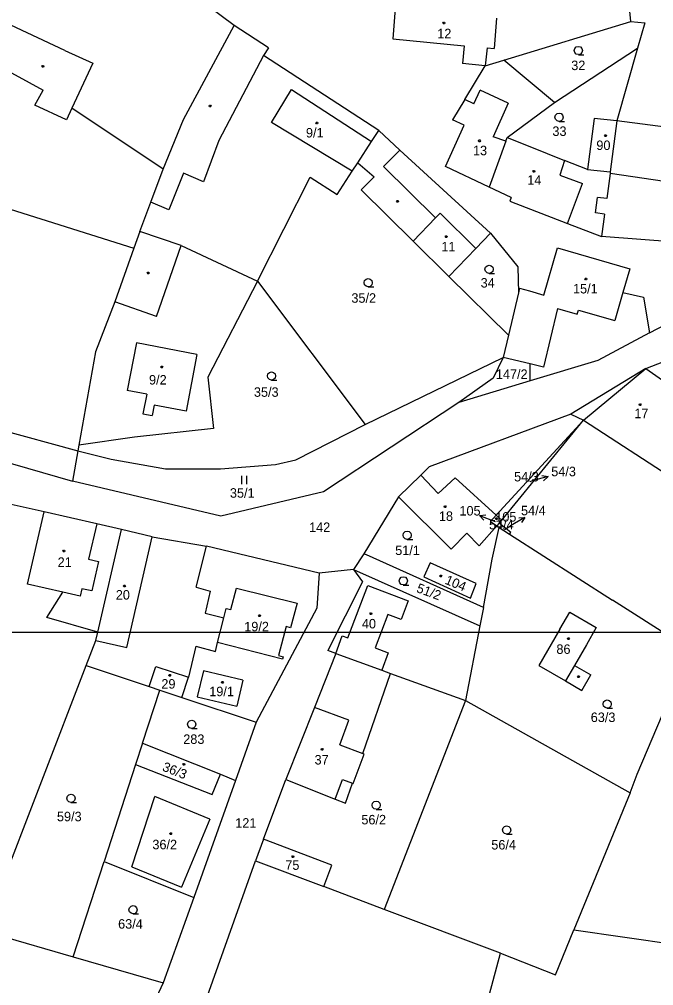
# Model space of a CAD drawing. Extents: x -752500 to -750336, y -1035826 to -1033500.
# Drawn here: x -751497.1 to -751383.4, y -1034563.3 to -1034390.2 of the extents above; entities that cross this region are included whole.
import ezdxf

# ---------------------------------------------------------------- set-up
doc = ezdxf.new("R2010")
doc.units = 0
for name, color, linetype in [('Default', 7, 'Continuous'), ('Hranice parcel', 7, 'Continuous'), ('ML1000', 7, 'Continuous'), ('Parcelní čísla', 7, 'Continuous'), ('Pop  PČ popisy', 7, 'Continuous'), ('Vnitřní kresba', 7, 'Continuous'), ('Značky budov', 7, 'Continuous'), ('Značky kultur', 7, 'Continuous')]:
    doc.layers.add(name, color=color, linetype=linetype)

# ---------------------------------------------------------------- blocks, each defined once
blk = doc.blocks.new('304')
at = {"layer": 'Default'}
blk.add_lwpolyline([(0, 0), (-0.38, 0.1), (-0.65, 0.37), (-0.75, 0.74), (-0.65, 1.11), (-0.38, 1.38), (-0.01, 1.48), (0.36, 1.38), (0.63, 1.11), (0.73, 0.73), (0.63, 0.35), (0.36, 0.08), (-0.02, -0.02), (0.98, -0.02)], dxfattribs=at)
blk = doc.blocks.new('306')
at = {"layer": 'Default'}
for p, q in [((-0.5, 1.5), (-0.5, 0)), ((0.5, 0), (0.5, 1.5))]:
    blk.add_line(p, q, dxfattribs=at)
blk = doc.blocks.new('10292')
at = {"layer": 'Default'}
blk.add_line((0, 3), (0, 0), dxfattribs=at)
blk.add_lwpolyline([(-0.5, 2), (0, 3), (0.5, 2)], dxfattribs=at)
blk = doc.blocks.new('402')
at = {"layer": 'Default'}
blk.add_lwpolyline([(0.09, 0.15), (0.18, 0), (0.09, -0.15), (-0.09, -0.15), (-0.18, 0), (-0.09, 0.15), (0.09, 0.15)], dxfattribs=at)

msp = doc.modelspace()

# ---------------------------------------------------------------- linework, layer by layer
at = {"layer": 'Hranice parcel'}
for p, q in [((-751387.54, -1034390.53), (-751392.08, -1034345.98)), ((-751458.62, -1034391.29), (-751473.53, -1034380.16)), ((-751429.76, -1034388.21), (-751430.17, -1034393.66)), ((-751411.64, -1034389.95), (-751412.05, -1034395.4)), ((-751467.72, -1034408.09), (-751458.62, -1034391.29)), ((-751452.45, -1034395.3), (-751458.62, -1034391.29)), ((-751410.32, -1034397.48), (-751387.54, -1034390.53)), ((-751387.54, -1034390.53), (-751385.01, -1034390.77)), ((-751385.01, -1034390.77), (-751386.32, -1034395.35)), ((-751430.17, -1034393.66), (-751417.38, -1034394.89)), ((-751452.45, -1034395.3), (-751453.35, -1034396.68)), ((-751417.38, -1034394.89), (-751417.69, -1034398.1)), ((-751413.31, -1034395.28), (-751413.62, -1034398.49)), ((-751413.31, -1034395.28), (-751412.05, -1034395.4)), ((-751401.21, -1034405.06), (-751386.32, -1034395.35)), ((-751386.32, -1034395.35), (-751390.04, -1034408.37)), ((-751503.65, -1034396.98), (-751492.88, -1034402.89)), ((-751432.72, -1034410.1), (-751453.35, -1034396.68)), ((-751413.62, -1034398.49), (-751417.69, -1034398.1)), ((-751417.32, -1034404.55), (-751413.62, -1034398.49)), ((-751413.62, -1034398.49), (-751410.32, -1034397.48)), ((-751401.21, -1034405.06), (-751410.32, -1034397.48)), ((-751494.34, -1034405.55), (-751492.88, -1034402.89)), ((-751488.67, -1034408.15), (-751494.34, -1034405.55)), ((-751417.32, -1034404.55), (-751419.52, -1034408.16)), ((-751409.71, -1034411.34), (-751401.21, -1034405.06)), ((-751487.71, -1034406.09), (-751488.67, -1034408.15)), ((-751471.36, -1034416.99), (-751487.71, -1034406.09)), ((-751545.55, -1034409.5), (-751476.6, -1034431.17)), ((-751471.36, -1034416.99), (-751467.72, -1034408.09)), ((-751420.76, -1034416.53), (-751417.41, -1034409.16)), ((-751417.41, -1034409.16), (-751419.52, -1034408.16)), ((-751394.13, -1034407.93), (-751395.28, -1034417.1)), ((-751390.04, -1034408.37), (-751394.13, -1034407.93)), ((-751390.04, -1034408.37), (-751391.23, -1034417.5)), ((-751375.36, -1034410.28), (-751390.04, -1034408.37)), ((-751434, -1034412.07), (-751432.72, -1034410.1)), ((-751428.93, -1034413.59), (-751432.72, -1034410.1)), ((-751436.49, -1034415.89), (-751434, -1034412.07)), ((-751409.94, -1034411.98), (-751412.91, -1034420.24)), ((-751409.94, -1034411.98), (-751409.71, -1034411.34)), ((-751409.71, -1034411.34), (-751405.63, -1034412.97)), ((-751405.63, -1034412.97), (-751399.43, -1034415.45)), ((-751412.7, -1034428.51), (-751428.93, -1034413.59)), ((-751437.46, -1034417.39), (-751436.49, -1034415.89)), ((-751436.49, -1034415.89), (-751433.53, -1034418.37)), ((-751395.28, -1034417.1), (-751399.43, -1034415.45)), ((-751473.58, -1034422.94), (-751471.36, -1034416.99)), ((-751440.17, -1034421.57), (-751437.46, -1034417.39)), ((-751412.91, -1034420.24), (-751420.76, -1034416.53)), ((-751395.28, -1034417.1), (-751391.23, -1034417.5)), ((-751391.27, -1034417.77), (-751391.87, -1034422.29)), ((-751391.23, -1034417.5), (-751391.27, -1034417.77)), ((-751454.46, -1034437.09), (-751444.98, -1034418.44)), ((-751444.98, -1034418.44), (-751440.17, -1034421.57)), ((-751433.53, -1034418.37), (-751435.87, -1034420.74)), ((-751426.54, -1034429.94), (-751435.87, -1034420.74)), ((-751408.96, -1034422.1), (-751412.91, -1034420.24)), ((-751475.53, -1034428.16), (-751473.58, -1034422.94)), ((-751408.96, -1034422.1), (-751409.23, -1034422.75)), ((-751409.23, -1034422.75), (-751398.89, -1034426.73)), ((-751393.88, -1034424.85), (-751393.51, -1034422.07)), ((-751391.87, -1034422.29), (-751393.51, -1034422.07)), ((-751392.24, -1034425.07), (-751393.88, -1034424.85)), ((-751392.24, -1034425.07), (-751392.78, -1034429.08)), ((-751398.89, -1034426.73), (-751392.78, -1034429.08)), ((-751475.53, -1034428.16), (-751476.6, -1034431.17)), ((-751468.14, -1034430.72), (-751475.53, -1034428.16)), ((-751415.29, -1034431.21), (-751412.7, -1034428.51)), ((-751412.7, -1034428.51), (-751407.8, -1034434.51)), ((-751420.13, -1034436.26), (-751426.54, -1034429.94)), ((-751370.18, -1034430.8), (-751392.78, -1034429.08)), ((-751476.6, -1034431.17), (-751480.01, -1034440.76)), ((-751468.14, -1034430.72), (-751454.46, -1034437.09)), ((-751420.13, -1034436.26), (-751415.29, -1034431.21)), ((-751403.15, -1034439.58), (-751400.71, -1034431.13)), ((-751400.71, -1034431.13), (-751387.74, -1034434.86)), ((-751407.8, -1034434.51), (-751407.68, -1034439.17)), ((-751387.74, -1034434.86), (-751388.96, -1034439.1)), ((-751454.46, -1034437.09), (-751463.33, -1034454.26)), ((-751454.46, -1034437.09), (-751435.16, -1034462.74)), ((-751420.13, -1034436.26), (-751409.47, -1034446.77)), ((-751407.48, -1034438.34), (-751407.68, -1034439.17)), ((-751407.48, -1034438.34), (-751405.73, -1034438.84)), ((-751405.73, -1034438.84), (-751403.15, -1034439.58)), ((-751407.68, -1034439.17), (-751409.47, -1034446.77)), ((-751388.96, -1034439.1), (-751385.3, -1034439.93)), ((-751385.3, -1034439.93), (-751384.22, -1034446.36)), ((-751384.22, -1034446.36), (-751372.58, -1034440.28)), ((-751480.01, -1034440.76), (-751483.5, -1034449.77)), ((-751409.47, -1034446.77), (-751410.41, -1034450.78)), ((-751384.22, -1034446.36), (-751393.43, -1034451.28)), ((-751384.87, -1034452.74), (-751371.68, -1034447.63)), ((-751483.5, -1034449.77), (-751486.47, -1034466.47)), ((-751435.16, -1034462.74), (-751410.41, -1034450.78)), ((-751410.41, -1034450.78), (-751412.2, -1034454.45)), ((-751405.6, -1034451.91), (-751410.41, -1034450.78)), ((-751405.57, -1034454.96), (-751405.6, -1034451.91)), ((-751393.43, -1034451.28), (-751405.57, -1034454.96)), ((-751384.87, -1034452.74), (-751398.3, -1034460.92)), ((-751552.12, -1034454.31), (-751487.6, -1034472.9)), ((-751463.33, -1034454.26), (-751462.3, -1034463.47)), ((-751412.2, -1034454.45), (-751418.39, -1034458.85)), ((-751529.41, -1034455.82), (-751486.65, -1034467.5)), ((-751405.57, -1034454.96), (-751418.39, -1034458.85)), ((-751418.39, -1034458.85), (-751442.6, -1034474.85)), ((-751398.3, -1034460.92), (-751423.67, -1034470.33)), ((-751398.3, -1034460.92), (-751396.05, -1034461.98)), ((-751447.56, -1034469.09), (-751435.16, -1034462.74)), ((-751396.05, -1034461.98), (-751411.67, -1034479.01)), ((-751410.68, -1034479.91), (-751396.05, -1034461.98)), ((-751396.05, -1034461.98), (-751362.12, -1034484.02)), ((-751462.3, -1034463.47), (-751476.48, -1034465.03)), ((-751486.47, -1034466.47), (-751486.65, -1034467.5)), ((-751476.48, -1034465.03), (-751486.47, -1034466.47)), ((-751486.65, -1034467.5), (-751487.6, -1034472.9)), ((-751486.65, -1034467.5), (-751480.67, -1034468.96)), ((-751480.67, -1034468.96), (-751470.96, -1034470.7)), ((-751461.06, -1034470.72), (-751451.22, -1034469.91)), ((-751451.22, -1034469.91), (-751447.56, -1034469.09)), ((-751470.96, -1034470.7), (-751461.06, -1034470.72)), ((-751425.2, -1034471.84), (-751429.16, -1034475.74)), ((-751423.67, -1034470.33), (-751425.2, -1034471.84)), ((-751461, -1034479.17), (-751487.6, -1034472.9)), ((-751442.6, -1034474.85), (-751461, -1034479.17)), ((-751492.7, -1034478.41), (-751498.58, -1034477.07)), ((-751429.16, -1034475.74), (-751435.4, -1034485.96)), ((-751429.16, -1034475.74), (-751419.74, -1034485.07)), ((-751495.67, -1034491.37), (-751492.7, -1034478.41)), ((-751483.25, -1034480.58), (-751492.7, -1034478.41)), ((-751412.72, -1034480.15), (-751411.67, -1034479.01)), ((-751412.72, -1034480.15), (-751411.57, -1034480.92)), ((-751410.68, -1034479.91), (-751411.67, -1034479.01)), ((-751411.13, -1034480.44), (-751411.57, -1034480.92)), ((-751411.13, -1034480.44), (-751410.68, -1034479.91)), ((-751409.07, -1034482.13), (-751411.13, -1034480.44)), ((-751478.83, -1034481.59), (-751483.25, -1034480.58)), ((-751483.06, -1034499.96), (-751478.83, -1034481.59)), ((-751473.31, -1034482.86), (-751478.83, -1034481.59)), ((-751419.74, -1034485.07), (-751416.92, -1034482.23)), ((-751416.92, -1034482.23), (-751414.72, -1034484.5)), ((-751414.72, -1034484.5), (-751411.57, -1034480.92)), ((-751412.37, -1034486.89), (-751411.13, -1034481.21)), ((-751411.57, -1034480.92), (-751411.13, -1034481.21)), ((-751411.13, -1034481.21), (-751409.3, -1034482.43)), ((-751409.3, -1034482.43), (-751409.07, -1034482.13)), ((-751473.31, -1034482.86), (-751463.61, -1034484.58)), ((-751409.3, -1034482.43), (-751390.83, -1034494.22)), ((-751465.41, -1034491.93), (-751463.61, -1034484.58)), ((-751443.41, -1034489.38), (-751463.61, -1034484.58)), ((-751435.4, -1034485.96), (-751437.22, -1034488.72)), ((-751434.91, -1034486.13), (-751435.4, -1034485.96)), ((-751413.93, -1034495.54), (-751434.91, -1034486.13)), ((-751413.93, -1034495.54), (-751412.37, -1034486.89)), ((-751437.22, -1034488.72), (-751443.41, -1034489.38)), ((-751437.22, -1034488.72), (-751414.59, -1034498.86)), ((-751437.22, -1034488.72), (-751435.64, -1034490.95)), ((-751423.49, -1034487.56), (-751424.62, -1034490.07)), ((-751415.26, -1034491.25), (-751423.49, -1034487.56)), ((-751443.41, -1034489.38), (-751443.8, -1034495.65)), ((-751424.62, -1034490.07), (-751416.28, -1034493.87)), ((-751489.33, -1034492.83), (-751495.67, -1034491.37)), ((-751465.41, -1034491.93), (-751462.91, -1034492.6)), ((-751462.91, -1034492.6), (-751463.84, -1034496.58)), ((-751459.24, -1034495.93), (-751458.19, -1034492.07)), ((-751458.19, -1034492.07), (-751447.32, -1034494.8)), ((-751435.64, -1034490.95), (-751441.86, -1034503.27)), ((-751416.28, -1034493.87), (-751415.26, -1034491.25)), ((-751492.2, -1034497.36), (-751489.33, -1034492.83)), ((-751377.1, -1034503.02), (-751390.83, -1034494.22)), ((-751460.49, -1034497.39), (-751460.06, -1034495.71)), ((-751460.06, -1034495.71), (-751459.24, -1034495.93)), ((-751443.8, -1034495.65), (-751454.69, -1034516.09)), ((-751447.32, -1034494.8), (-751448.51, -1034499.17)), ((-751413.93, -1034495.54), (-751414.59, -1034498.86)), ((-751483.06, -1034499.96), (-751492.2, -1034497.36)), ((-751463.84, -1034496.58), (-751460.49, -1034497.39)), ((-751461.62, -1034501.81), (-751460.49, -1034497.39)), ((-751400.25, -1034499.43), (-751398.49, -1034496.38)), ((-751398.49, -1034496.38), (-751393.74, -1034499.14)), ((-751449.33, -1034498.96), (-751450.66, -1034504.15)), ((-751448.51, -1034499.17), (-751449.33, -1034498.96)), ((-751414.59, -1034498.86), (-751417.19, -1034512.23)), ((-751400.25, -1034499.43), (-751404.02, -1034505.95)), ((-751393.74, -1034499.14), (-751395.51, -1034502.22)), ((-751483.41, -1034501.47), (-751483.06, -1034499.96)), ((-751485.13, -1034505.95), (-751483.41, -1034501.47)), ((-751465.5, -1034502.48), (-751466.8, -1034508.06)), ((-751465.5, -1034502.48), (-751461.99, -1034503.41)), ((-751461.99, -1034503.41), (-751461.62, -1034501.81)), ((-751449.94, -1034504.8), (-751461.62, -1034501.81)), ((-751395.51, -1034502.22), (-751397.65, -1034505.94)), ((-751450.66, -1034504.15), (-751449.83, -1034504.36)), ((-751449.83, -1034504.36), (-751449.94, -1034504.8)), ((-751440.4, -1034503.8), (-751444.22, -1034513.48)), ((-751440.4, -1034503.8), (-751441.86, -1034503.27)), ((-751440.4, -1034503.8), (-751432.17, -1034506.8)), ((-751503.46, -1034553.49), (-751485.13, -1034505.95)), ((-751485.13, -1034505.95), (-751473.86, -1034509.71)), ((-751473.86, -1034509.71), (-751472.65, -1034506.11)), ((-751472.65, -1034506.11), (-751466.8, -1034508.06)), ((-751404.02, -1034505.95), (-751399.25, -1034508.71)), ((-751397.65, -1034505.94), (-751394.71, -1034507.63)), ((-751468.01, -1034511.66), (-751466.8, -1034508.06)), ((-751435.59, -1034521.7), (-751430.59, -1034507.37)), ((-751432.17, -1034506.8), (-751430.59, -1034507.37)), ((-751430.59, -1034507.37), (-751417.19, -1034512.23)), ((-751396.3, -1034510.41), (-751394.71, -1034507.63)), ((-751473.86, -1034509.71), (-751471.97, -1034510.34)), ((-751399.25, -1034508.71), (-751396.3, -1034510.41)), ((-751475.05, -1034519.83), (-751471.97, -1034510.34)), ((-751471.97, -1034510.34), (-751468.01, -1034511.66)), ((-751468.01, -1034511.66), (-751454.69, -1034516.09)), ((-751417.19, -1034512.23), (-751431.72, -1034549.64)), ((-751417.19, -1034512.23), (-751387.67, -1034528.74)), ((-751444.22, -1034513.48), (-751449.35, -1034526.39)), ((-751386.39, -1034525.42), (-751381.87, -1034514.7)), ((-751454.69, -1034516.09), (-751458.41, -1034526.52)), ((-751475.05, -1034519.83), (-751476.29, -1034523.66)), ((-751475.05, -1034519.83), (-751461.1, -1034525.44)), ((-751437.28, -1034527.1), (-751435.3, -1034521.81)), ((-751435.3, -1034521.81), (-751435.59, -1034521.7)), ((-751476.29, -1034523.66), (-751481.93, -1034541.04)), ((-751476.29, -1034523.66), (-751462.54, -1034529.07)), ((-751462.54, -1034529.07), (-751461.1, -1034525.44)), ((-751461.1, -1034525.44), (-751458.41, -1034526.52)), ((-751387.67, -1034528.74), (-751386.39, -1034525.42)), ((-751458.41, -1034526.52), (-751465.87, -1034547.5)), ((-751453.37, -1034537.07), (-751449.35, -1034526.39)), ((-751449.35, -1034526.39), (-751440.51, -1034529.86)), ((-751438.68, -1034530.58), (-751437.44, -1034527.04)), ((-751437.44, -1034527.04), (-751437.28, -1034527.1)), ((-751387.67, -1034528.74), (-751397.73, -1034553.31)), ((-751440.51, -1034529.86), (-751438.68, -1034530.58)), ((-751453.37, -1034537.07), (-751454.81, -1034540.92)), ((-751441.12, -1034541.71), (-751453.37, -1034537.07)), ((-751487.48, -1034558.11), (-751481.93, -1034541.04)), ((-751481.93, -1034541.04), (-751465.87, -1034547.5)), ((-751463.42, -1034565.13), (-751454.81, -1034540.92)), ((-751454.81, -1034540.92), (-751442.57, -1034545.54)), ((-751442.57, -1034545.54), (-751441.12, -1034541.71)), ((-751431.72, -1034549.64), (-751442.57, -1034545.54)), ((-751465.87, -1034547.5), (-751471.33, -1034562.81)), ((-751410.9, -1034557.5), (-751431.72, -1034549.64)), ((-751503.46, -1034553.49), (-751487.48, -1034558.11)), ((-751401.02, -1034561.34), (-751397.73, -1034553.31)), ((-751397.73, -1034553.31), (-751272.79, -1034571.27)), ((-751487.48, -1034558.11), (-751471.33, -1034562.81)), ((-751421.27, -1034596.11), (-751410.9, -1034557.5)), ((-751410.9, -1034557.5), (-751401.02, -1034561.34)), ((-751471.33, -1034562.81), (-751488.49, -1034598.68))]:
    msp.add_line(p, q, dxfattribs=at)
at = {"layer": 'ML1000'}
msp.add_lwpolyline([(-751250, -1034500), (-751875, -1034500), (-752500, -1034500)], dxfattribs=at)
at = {"layer": 'Pop  PČ popisy'}
for p, q in [((-751405.58, -1034472.96), (-751405.28, -1034472.88)), ((-751410.17, -1034481.55), (-751409.11, -1034480.93))]:
    msp.add_line(p, q, dxfattribs=at)
at = {"layer": 'Vnitřní kresba'}
for p, q in [((-751488.96, -1034395.74), (-751500.54, -1034390.33)), ((-751488.96, -1034395.74), (-751483.94, -1034398.02)), ((-751453.35, -1034396.68), (-751461.36, -1034411.9)), ((-751483.94, -1034398.02), (-751487.71, -1034406.09)), ((-751451.91, -1034408.63), (-751448.34, -1034402.74)), ((-751448.34, -1034402.74), (-751434, -1034412.07)), ((-751415.67, -1034405.33), (-751414.55, -1034402.87)), ((-751409.5, -1034405.17), (-751414.55, -1034402.87)), ((-751415.67, -1034405.33), (-751417.32, -1034404.55)), ((-751409.5, -1034405.17), (-751412.22, -1034411.23)), ((-751437.46, -1034417.39), (-751451.91, -1034408.63)), ((-751409.94, -1034411.98), (-751412.22, -1034411.23)), ((-751461.36, -1034411.9), (-751464.15, -1034419.31)), ((-751399.43, -1034415.45), (-751400.28, -1034418.08)), ((-751467.73, -1034417.71), (-751470.35, -1034424.33)), ((-751464.15, -1034419.31), (-751467.73, -1034417.71)), ((-751400.28, -1034418.08), (-751396.19, -1034419.61)), ((-751376.63, -1034419.94), (-751391.27, -1034417.77)), ((-751398.89, -1034426.73), (-751396.19, -1034419.61)), ((-751470.35, -1034424.33), (-751473.58, -1034422.94)), ((-751422.52, -1034425.75), (-751426.54, -1034429.94)), ((-751472.54, -1034443.42), (-751468.14, -1034430.72)), ((-751388.96, -1034439.1), (-751390.41, -1034444.14)), ((-751472.54, -1034443.42), (-751480.01, -1034440.76)), ((-751400.7, -1034441.96), (-751403.18, -1034452.48)), ((-751400.7, -1034441.96), (-751397.15, -1034442.98)), ((-751397.15, -1034442.98), (-751396.94, -1034442.26)), ((-751396.94, -1034442.26), (-751390.41, -1034444.14)), ((-751476.15, -1034448.16), (-751477.78, -1034456.69)), ((-751465.31, -1034450.23), (-751476.15, -1034448.16)), ((-751465.31, -1034450.23), (-751467.25, -1034460.38)), ((-751403.18, -1034452.48), (-751405.6, -1034451.91)), ((-751396.05, -1034461.98), (-751384.87, -1034452.74)), ((-751384.87, -1034452.74), (-751377.51, -1034457.92)), ((-751474.3, -1034457.35), (-751477.78, -1034456.69)), ((-751474.3, -1034457.35), (-751474.97, -1034460.83)), ((-751472.95, -1034459.29), (-751473.3, -1034461.15)), ((-751467.25, -1034460.38), (-751472.95, -1034459.29)), ((-751474.97, -1034460.83), (-751473.3, -1034461.15)), ((-751425.2, -1034471.84), (-751422.08, -1034475.11)), ((-751422.08, -1034475.11), (-751419.05, -1034472.29)), ((-751419.05, -1034472.29), (-751411.67, -1034479.01)), ((-751483.25, -1034480.58), (-751484.7, -1034486.92)), ((-751477.88, -1034502.74), (-751473.31, -1034482.86)), ((-751484.7, -1034486.92), (-751482.95, -1034487.32)), ((-751482.95, -1034487.32), (-751484.15, -1034492.58)), ((-751485.91, -1034492.18), (-751486.22, -1034493.54)), ((-751484.15, -1034492.58), (-751485.91, -1034492.18)), ((-751438.28, -1034500.96), (-751434.68, -1034491.59)), ((-751434.68, -1034491.59), (-751427.46, -1034494.36)), ((-751486.22, -1034493.54), (-751489.33, -1034492.83)), ((-751427.46, -1034494.36), (-751428.72, -1034497.7)), ((-751431.08, -1034496.79), (-751433.38, -1034502.8)), ((-751428.72, -1034497.7), (-751431.08, -1034496.79)), ((-751440.4, -1034503.8), (-751439.27, -1034500.6)), ((-751439.27, -1034500.6), (-751438.28, -1034500.96)), ((-751483.41, -1034501.47), (-751477.88, -1034502.74)), ((-751433.38, -1034502.8), (-751431, -1034503.65)), ((-751431, -1034503.65), (-751432.17, -1034506.8)), ((-751397.65, -1034505.94), (-751399.25, -1034508.71)), ((-751464.14, -1034506.89), (-751465.25, -1034511.55)), ((-751457.05, -1034508.57), (-751464.14, -1034506.89)), ((-751457.05, -1034508.57), (-751458.16, -1034513.24)), ((-751465.25, -1034511.55), (-751458.16, -1034513.24)), ((-751438.07, -1034515.74), (-751444.22, -1034513.48)), ((-751439.71, -1034520.18), (-751438.07, -1034515.74)), ((-751439.71, -1034520.18), (-751435.59, -1034521.7)), ((-751440.51, -1034529.86), (-751439.22, -1034526.35)), ((-751439.22, -1034526.35), (-751437.44, -1034527.04)), ((-751476.99, -1034542.04), (-751472.85, -1034529.39)), ((-751462.98, -1034533.47), (-751472.85, -1034529.39)), ((-751462.98, -1034533.47), (-751468.04, -1034545.64)), ((-751476.99, -1034542.04), (-751468.04, -1034545.64))]:
    msp.add_line(p, q, dxfattribs=at)
for points in [[(-751422.52, -1034425.75), (-751431.86, -1034416.55), (-751428.93, -1034413.59)], [(-751415.29, -1034431.21), (-751421.69, -1034424.89), (-751422.52, -1034425.75)]]:
    msp.add_lwpolyline(points, dxfattribs=at)

# ---------------------------------------------------------------- block references
at = {"layer": 'Pop  PČ popisy'}
for p, rotation in [((-751405.28, -1034472.88), -75.068088), ((-751411.86, -1034480.16), 68.69764), ((-751409.11, -1034480.93), -59.54093199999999)]:
    msp.add_blockref('10292', p, dxfattribs=dict(at, rotation=rotation))
at = {"layer": 'Značky budov'}
for p in [(-751421.03, -1034390.83), (-751492.89, -1034398.62), (-751462.95, -1034405.7), (-751443.79, -1034408.72), (-751392.07, -1034411.03), (-751414.69, -1034411.94), (-751404.91, -1034417.41), (-751429.35, -1034422.76), (-751420.61, -1034429.13), (-751474.02, -1034435.64), (-751395.58, -1034436.68), (-751471.59, -1034452.49), (-751385.89, -1034459.21), (-751420.84, -1034477.49), (-751411.64, -1034479.65), (-751489.14, -1034485.43), (-751421.61, -1034489.93), (-751478.3, -1034491.68), (-751454.08, -1034497.01), (-751434.13, -1034496.68), (-751398.72, -1034501.14), (-751470.16, -1034507.72), (-751396.92, -1034507.94), (-751460.74, -1034508.94), (-751442.87, -1034520.98), (-751467.63, -1034523.65), (-751469.98, -1034536.08), (-751448.11, -1034540.2)]:
    msp.add_blockref('402', p, dxfattribs=at)
at = {"layer": 'Značky kultur'}
for name, p in [('304', (-751396.93, -1034396.49)), ('304', (-751400.39, -1034408.45)), ('304', (-751412.93, -1034435.69)), ('304', (-751434.6, -1034438.09)), ('304', (-751451.93, -1034454.8)), ('306', (-751456.83, -1034473.44)), ('304', (-751427.61, -1034483.34)), ('304', (-751428.31, -1034491.51)), ('304', (-751391.78, -1034513.59)), ('304', (-751466.22, -1034517.21)), ('304', (-751487.85, -1034530.47)), ('304', (-751433.17, -1034531.7)), ('304', (-751409.79, -1034536.15)), ('304', (-751476.73, -1034550.44))]:
    msp.add_blockref(name, p, dxfattribs=at)

# ---------------------------------------------------------------- texts
at = {"layer": 'Parcelní čísla'}
for s, p in [('12', (-751422.23, -1034393.56)), ('32', (-751398.22, -1034399.27)), ('9/1', (-751445.76, -1034411.34)), ('33', (-751401.6, -1034411.06)), ('13', (-751415.83, -1034414.52)), ('90', (-751393.72, -1034413.58)), ('14', (-751406.1, -1034419.81)), ('11', (-751421.5, -1034431.75)), ('34', (-751414.46, -1034438.23)), ('15/1', (-751397.91, -1034439.28)), ('35/2', (-751437.62, -1034440.95)), ('147/2', (-751411.73, -1034454.6)), ('9/2', (-751473.88, -1034455.6)), ('35/3', (-751455.09, -1034457.8)), ('17', (-751386.92, -1034461.63)), ('54/3', (-751408.46, -1034472.96)), ('54/3', (-751401.81, -1034472.03)), ('35/1', (-751459.39, -1034475.88)), ('18', (-751421.94, -1034480.03)), ('105', (-751418.26, -1034479.07)), ('105', (-751411.84, -1034480.16)), ('54/4', (-751407.22, -1034479.03)), ('142', (-751445.2, -1034482.02)), ('54/4', (-751412.96, -1034481.55)), ('51/1', (-751429.77, -1034486.15)), ('21', (-751490.26, -1034488.27)), ('20', (-751479.84, -1034494.13)), ('40', (-751435.74, -1034499.3)), ('19/2', (-751456.82, -1034499.82)), ('86', (-751400.88, -1034503.86)), ('29', (-751471.67, -1034510.08)), ('19/1', (-751463.09, -1034511.44)), ('63/3', (-751394.73, -1034516.07)), ('283', (-751467.75, -1034519.99)), ('37', (-751444.22, -1034523.68)), ('59/3', (-751490.38, -1034533.85)), ('121', (-751458.43, -1034535)), ('56/2', (-751435.83, -1034534.41)), ('36/2', (-751473.28, -1034538.87)), ('56/4', (-751412.55, -1034538.91)), ('75', (-751449.46, -1034542.55)), ('63/4', (-751479.42, -1034553.09))]:
    msp.add_text(s, height=1.7, dxfattribs=at).set_placement(p)
for s, rotation, p in [('104', 337.3, (-751420.99, -1034491.25)), ('51/2', 339.707, (-751426.09, -1034492.75)), ('36/3', 338.675, (-751471.63, -1034524.74))]:
    msp.add_text(s, height=1.7, rotation=rotation, dxfattribs=at).set_placement(p)

doc.saveas('drawing.dxf')
